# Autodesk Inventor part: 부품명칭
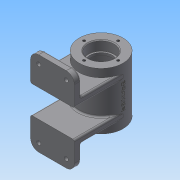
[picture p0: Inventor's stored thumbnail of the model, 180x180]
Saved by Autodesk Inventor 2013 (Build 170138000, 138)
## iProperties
Created: 2017-02
Part Number: 부품명칭
Material: Generic
Document SubType Name: Modeling
Designer: Administrator
Density: 1 g/cm^3
Author: Administrator
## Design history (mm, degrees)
sketch "스케치1"
  geometry: C1 r 27 at (0, 0); 1 further point
  constraints: 1 centre point, 1 coincident
  dimensions: "d0" = 54 diameter of C1
extrude "돌출1" new body sketch "스케치1" stored distance "d1" = 70; taper "d2" = 0 deg
node "작업 평면1"
sketch "스케치2"
  geometry: L1 (27, 17)-(-27, 17); L2 (-27, 17)-(-27, 52); L3 (-27, 52)-(27, 52); L4 (27, 52)-(27, 17); 1 further point
  constraints: 8 end point, 2 parallel, 1 horizontal, 1 perpendicular
  dimensions: "d4" = 17 distance from line of point (0, 0) L1; "d5" = 54 distance of L2.end L3.end; "d6" = 27 distance from line of point (0, 0) L2; "d7" = 35 distance of L1.end L2.end
extrude "돌출2" join sketch "스케치2" distance "d8" = 8; taper "d9" = 0 deg
sketch "스케치3"
  geometry: L1 (-27, -17)-(27, -17); L2 (27, -17)-(27, -25); L3 (27, -25)-(-27, -25); L4 (-27, -25)-(-27, -17); 1 further point
  constraints: 8 end point, 2 parallel, 1 horizontal, 1 perpendicular
  dimensions: "d10" = 54 distance of L2.end L3.end; "d11" = 8 distance of L1.end L2.end
extrude "돌출3" join sketch "스케치3" stored distance "d12" = 8; taper "d13" = 0 deg
sketch "스케치4"
  geometry: C1 r 2.5 at (-17, -42); 1 further point
  constraints: 1 centre point
  dimensions: "d14" = 5 diameter of C1; "d15" = 17 horizontal distance of point (0, 0) C1.centre; "d16" = 42 vertical distance of point (0, 0) C1.centre
extrude "돌출4" cut sketch "스케치4" distance "d17" = 8; taper "d18" = 0 deg
sketch "스케치6"
  geometry: L1 (-12.5, -44.598)-(-17, -47.196); L2 (-17, -47.196)-(-21.5, -44.598); L3 (-21.5, -44.598)-(-21.5, -39.402); L4 (-21.5, -39.402)-(-17, -36.804); L5 (-17, -36.804)-(-12.5, -39.402); L6 (-12.5, -39.402)-(-12.5, -44.598); C1 r 2.5 at (-17, -42) reference; 3 further points
  constraints: 12 end point, 1 midpoint, 13 other
extrude "돌출5" cut sketch "스케치6" distance "d20" = 3; taper "d21" = 0 deg
fillet "모깎기1" dims "d22" = 10
node "작업 평면2"
sketch "스케치7"
  geometry: L1 (27, 35)-(-27, 35) reference; C1 r 5 at (0, 10); 1 further point
  constraints: 1 centre point
  dimensions: "d24" = 10 diameter of C1; "d25" = 25 distance from line of L1 C1.centre
extrude "돌출6" join sketch "스케치7" stored distance "d26" = 3; taper "d27" = 0 deg
sketch "스케치8"
  geometry: C1 r 27 at (0, 0) reference; C2 r 16 at (0, 0)
  constraints: 1 centre point, 1 coincident
  dimensions: "d28" = 32 diameter of C2
extrude "돌출7" cut sketch "스케치8" distance "d29" = 12; taper "d30" = 0 deg
sketch "스케치9"
  geometry: C1 r 16 at (0, 0) reference; C2 r 14 at (0, 0)
  constraints: 1 centre point, 1 coincident
  dimensions: "d31" = 28 diameter of C2
extrude "돌출8" cut sketch "스케치9" distance "d32" = 3; taper "d33" = 0 deg
sketch "스케치10"
  geometry: C1 r 14 at (0, 0) reference; C2 r 22 at (0, 0)
  constraints: 1 centre point, 1 coincident
  dimensions: "d34" = 44 diameter of C2
extrude "돌출9" cut sketch "스케치10" distance "d35" = 40; taper "d36" = 0 deg
hole "구멍1" diameter "d39" = 5.188; stored, may be unused: countersink angle "d43" = 90 deg, drill point angle "d45" = 118 deg; dims "d40" = 30, "d41" = 4, "d42" = 2, "d44" = 30, "d63" = 10, "d64" = 10
node "작업 평면3"
sketch "스케치12"
  geometry: 2 further points
  constraints: 1 coincident, 1 other
feature "엠보싱1" sketch "스케치12" dims "d12" = 8, "d13" = 0, "d47" = 0.5, "d48" = 0
sketch "스케치13"
  geometry: L1 (0, 0)-(-16.339, -25.16); L2 (0, 0)-(30, 0)
  constraints: 4 end point, 1 equal length, 1 horizontal
  dimensions: "d49" = 30 distance of L1.start L1.end; "d50" = 123 deg angle of L1 L2
node "작업 평면4"
sketch "스케치14"
  geometry: C1 r 6 at (0, 0); 1 further point
  constraints: 1 centre point, 1 coincident
  dimensions: "d51" = 12 diameter of C1
extrude "돌출10" join sketch "스케치14" stored distance "d52" = 40; taper "d53" = 0 deg
sketch "스케치15"
  geometry: C1 r 6 at (0, 0) reference
sketch "스케치16"
  geometry: C1 r 6 at (0, 0) reference
hole "구멍2" diameter "d56" = 5.188; stored, may be unused: countersink angle "d60" = 90 deg, drill point angle "d62" = 118 deg; dims "d54" = 10, "d55" = 10, "d57" = 30, "d58" = 4, "d59" = 2, "d61" = 30
sketch "스케치17"
  geometry: L1 (0, 0)-(0, 21); C1 r 27 at (0, 0) reference; 1 further point
  constraints: 2 end point, 1 coincident, 1 vertical
  dimensions: "d65" = 21 distance of L1.start L1.end
hole "구멍3" sketch "스케치17" at (0, 21) diameter "d66" = 3.242; stored, may be unused: countersink angle "d70" = 90 deg, drill point angle "d72" = 118 deg; dims "d67" = 8, "d68" = 4, "d69" = 2, "d71" = 10
fillet "모깎기2" dims "d76" = 10
fillet "모깎기3" dims "d77" = 2
fillet "모깎기4" dims "d78" = 2
fillet "모깎기5" dims "d79" = 2
fillet "모깎기6" dims "d80" = 2
fillet "모깎기7" dims "d81" = 2
fillet "모깎기8" dims "d82" = 0.3
chamfer "모따기1" distance "d83" = 1; stored, may be unused: second distance "d84" = 2, angle "d85" = 45 deg
fillet "모깎기9" dims "d86" = 2
fillet "모깎기10" dims "d87" = 2
fillet "모깎기11" dims "d88" = 2
node "솔리드1"
mirror "대칭1"
mirror "대칭2"
mirror "대칭3"
pattern_circular "원형 패턴1" dims angle "d74" = 360 deg
mirror "대칭4"
other parameters: "d23" = 32, "d46" = 27
